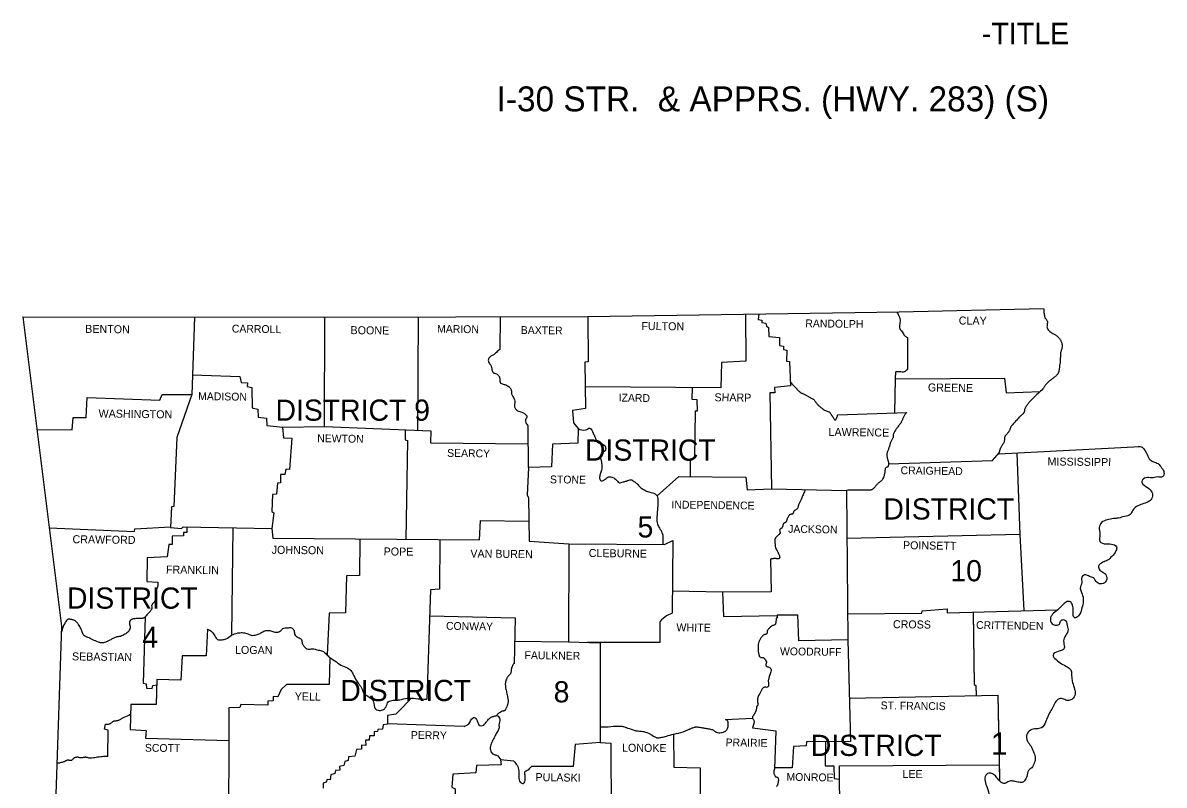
# Model space of a CAD drawing. Extents: x 541267 to 698737, y 790528 to 880942.
# Drawn here: x 637378 to 662478, y 852235 to 869007 of the extents above; entities that cross this region are included whole.
import ezdxf

# ---------------------------------------------------------------- set-up
doc = ezdxf.new("R2010")
doc.units = 0
doc.layers.add('R_Draft', color=7, linetype='Continuous')
doc.layers.add('R_Grid Annot', color=7, linetype='Continuous')

msp = doc.modelspace()

# ---------------------------------------------------------------- linework, layer by layer
at = {"layer": 'R_Draft'}
for p, q in [((656570, 861176), (656573, 861328)), ((658844, 859527), (658888, 859663)), ((653967, 855984), (654424, 855984))]:
    msp.add_line(p, q, dxfattribs=at)
for points in [[(637378, 862535), (643995, 862531), (649801, 862543), (656651, 862650), (659826, 862723)], [(637378, 862535), (638225, 855734), (637857, 844633)], [(641156, 862533), (641097, 860833)], [(641112, 861259), (642153, 861226), (642178, 861095), (642317, 861090), (642313, 861009), (642411, 860984), (642419, 860538), (642546, 860509), (642554, 860334), (642734, 860309), (642742, 860145), (643098, 860108), (644015, 860129), (644023, 862531)], [(646074, 862535), (646061, 860043)], [(647874, 862539), (647866, 861819)], [(649801, 862543), (649809, 861545), (649740, 861541), (649752, 860522), (649466, 860481), (649490, 860207), (649588, 860080), (649580, 859757), (649024, 859736), (649003, 859237), (648496, 859221), (648471, 858615), (648500, 858566), (648512, 857600), (649388, 857543), (649376, 855386), (650071, 855366), (650071, 853173), (649523, 853132), (649482, 852649), (648561, 852645)], [(653267, 862597), (653275, 861565), (652743, 861537), (652727, 860980), (649746, 860997)], [(653565, 862602), (653549, 862478), (653631, 862465), (653627, 862416), (653721, 862396), (653729, 862330), (653774, 862302), (653787, 862105), (654020, 862081), (654020, 861905), (654106, 861893), (654106, 861823), (654179, 861802), (654175, 861565), (654241, 861553), (654257, 861017), (653909, 860984), (653914, 860870), (653807, 860865), (653844, 858754), (655493, 858717), (655522, 855436), (654445, 855407), (654424, 855984)], [(656831, 862085), (656831, 861393)], [(656552, 860426), (656570, 861176), (656573, 861176), (658967, 861189), (659000, 860870), (659751, 860897)], [(652097, 860984), (652088, 860730), (652203, 860722), (652207, 860460), (652166, 860460), (652150, 859429), (652056, 859388), (652056, 859025)], [(637686, 860059), (638466, 860055), (638487, 860325), (638769, 860325), (638794, 860763), (640390, 860706), (640439, 860829), (641097, 860833), (640766, 859883), (640701, 858365), (640651, 858361), (640627, 857903), (640868, 857882), (640905, 857919), (642857, 857882), (642877, 857666)], [(655301, 860383), (656809, 860435)], [(643090, 860109), (643107, 859879), (643295, 859867), (643246, 859180), (643160, 859184), (643143, 859073), (643045, 859073), (643041, 858885), (642980, 858881), (642959, 858639), (642869, 858627), (642857, 858259), (642898, 858230), (642857, 857882)], [(644015, 860129), (646347, 860031), (646343, 859765), (648493, 859748)], [(645787, 860054), (645783, 859830), (645836, 859818), (645803, 857642)], [(648496, 859221), (648492, 860141)], [(658844, 859527), (661950, 859687)], [(656416, 859302), (658701, 859376), (658851, 859549)], [(659236, 859548), (659307, 857752), (659390, 856075)], [(651327, 858599), (651802, 859028), (653275, 859008), (653304, 858734), (653844, 858754)], [(656029, 858725), (655530, 858725), (655493, 858717)], [(642877, 857666), (647420, 857629), (647440, 858058), (648506, 858046)], [(637955, 857900), (639833, 857813), (639841, 857878), (640628, 857916)], [(640987, 857918), (640987, 857792), (640909, 857792), (640913, 857719), (640664, 857715), (640660, 857531), (640590, 857531), (640553, 857256), (640111, 857236), (640107, 856716), (640345, 856700)], [(641998, 857899), (641969, 855538)], [(659307, 857752), (655502, 857665)], [(644786, 857650), (644781, 856849), (644499, 856844), (644474, 856030), (644114, 856018), (644070, 855100)], [(646548, 857636), (646540, 856549), (646343, 856532), (646266, 854126)], [(649388, 857543), (651491, 857531), (651671, 857617), (651659, 856017), (651536, 855963), (651426, 855869), (651389, 855832), (651385, 855374), (649793, 855374)], [(653823, 857207), (653832, 856487), (652768, 856483), (651663, 856504)], [(652768, 856483), (652784, 855947), (653967, 855968)], [(640068, 855942), (640025, 854482), (640087, 854466), (640099, 854368), (640222, 854359), (640234, 854429), (640321, 854443)], [(646325, 855964), (648205, 855918), (648181, 854908)], [(653967, 855984), (653967, 855914), (653946, 855910)], [(655517, 856008), (657150, 856017), (657154, 856074), (657703, 856115), (657703, 856029), (660140, 856096)], [(658275, 856045), (658296, 854453), (658333, 854429), (658346, 854203)], [(658276, 856029), (658296, 854453), (658333, 854429), (658345, 854216)], [(658276, 856029), (658296, 854453), (658333, 854429), (658345, 854216)], [(658276, 856029), (658296, 854453), (658333, 854429), (658345, 854216)], [(658276, 856029), (658296, 854453), (658333, 854429), (658345, 854216)], [(641441, 855669), (641413, 855084), (640881, 855080), (640852, 854548), (640324, 854560), (640308, 854012), (639755, 854007), (639739, 853459), (640087, 853439), (640074, 853271), (641905, 853220)], [(655522, 855436), (655583, 853193), (654609, 853189), (654605, 853099), (654323, 853083), (654298, 852616), (653910, 852616)], [(648185, 855403), (649376, 855386)], [(644130, 855043), (644113, 854453), (643180, 854449), (643058, 854343), (642988, 854179), (642886, 854188), (642882, 854093), (642763, 854081), (642767, 853995), (642174, 854012), (642153, 853946), (641908, 853938), (641905, 853220)], [(655557, 854146), (658820, 854212)], [(658820, 854212), (658853, 852420)], [(658820, 854212), (658853, 852420)], [(658820, 854212), (658853, 852420)], [(658820, 854212), (658853, 852420)], [(658820, 854212), (658853, 852420)], [(658820, 854212), (658853, 852420)], [(658820, 854212), (658853, 852420)], [(658820, 854212), (658854, 852338)], [(645920, 854148), (645738, 853950), (645578, 853799), (645394, 853770), (645394, 853578), (645304, 853566), (645288, 853467), (645185, 853459), (645177, 853414), (645108, 853410), (645104, 853324), (645005, 853320), (644997, 853222), (644915, 853222), (644919, 853107), (644829, 853115), (644825, 853025), (644715, 853017), (644682, 852870), (644543, 852858), (644531, 852776), (644457, 852755), (644437, 852669), (644342, 852649), (644351, 852563), (644256, 852555), (644240, 852489), (644154, 852465), (644134, 852354), (644068, 852358), (644048, 852301), (643986, 852281), (643982, 852170)], [(652833, 853680), (653422, 853709)], [(639244, 852866), (639256, 853443), (639174, 853467), (639199, 853578)], [(647084, 853529), (645394, 853582)], [(653427, 853496), (653938, 853431), (653909, 852596)], [(641905, 853220), (641899, 851544), (641695, 851540), (641711, 851417), (641515, 851421), (641511, 851331), (641318, 851331), (641323, 851266), (641036, 851258), (641032, 851008), (640754, 851033), (640709, 849019), (639133, 849024), (639096, 848557), (639154, 848516), (639150, 847992), (637970, 848044)], [(650071, 853173), (650308, 853156), (650313, 851593), (650100, 850705), (650554, 850685), (650550, 849903)], [(651687, 853361), (651696, 852629), (652273, 852616), (652277, 851045)], [(655027, 853191), (655022, 852661), (655211, 852661), (655219, 852379), (655340, 852366)], [(648177, 852764), (647882, 852796), (647894, 852686), (647358, 852665), (647342, 852506), (646838, 852477), (646810, 852191), (646884, 852154), (646884, 851966)], [(655508, 849028), (655890, 849052), (655886, 849883), (655587, 849903), (655603, 851528), (655346, 851565), (655338, 852657), (658848, 852682)]]:
    msp.add_lwpolyline(points, dxfattribs=at)
for points in [[(659826, 862723), (659830, 862678), (659835, 862633), (659840, 862588), (659847, 862543), (659856, 862518), (659873, 862495), (659891, 862473), (659904, 862449), (659909, 862407), (659904, 862363), (659901, 862318), (659904, 862297), (659912, 862277), (659943, 862237), (659982, 862203), (660011, 862184), (660041, 862167), (660072, 862150), (660101, 862130), (660160, 862077), (660185, 862047), (660196, 862030), (660207, 862011), (660222, 861977), (660230, 861942), (660233, 861907), (660232, 861872), (660224, 861836), (660214, 861801), (660205, 861765), (660199, 861729), (660197, 861689), (660195, 861649), (660193, 861609), (660191, 861569), (660174, 861430), (660167, 861366), (660160, 861334), (660156, 861319), (660150, 861303), (660107, 861247), (660051, 861201), (660028, 861182), (660004, 861164), (659980, 861146), (659957, 861127), (659871, 861041), (659855, 861019), (659842, 860996), (659827, 860972), (659810, 860951), (659704, 860853), (659597, 860751), (659511, 860661), (659488, 860634), (659466, 860605), (659445, 860576), (659425, 860546), (659413, 860516), (659407, 860482), (659400, 860448), (659394, 860433), (659384, 860419), (659362, 860396), (659338, 860374), (659313, 860352), (659290, 860329), (659217, 860248), (659118, 860137), (659102, 860112), (659091, 860083), (659081, 860054), (659069, 860027), (659047, 859994), (659022, 859964), (658996, 859933), (658975, 859900), (658966, 859870), (658964, 859839), (658962, 859807), (658955, 859777), (658941, 859752), (658925, 859727), (658909, 859703), (658893, 859679), (658888, 859663)], [(656593, 862649), (656667, 862494), (656663, 862384), (656663, 862281), (656717, 862212), (656770, 862126), (656831, 862085)], [(647866, 861819), (647792, 861757), (647726, 861700), (647628, 861631), (647616, 861565), (647649, 861500), (647681, 861446), (647694, 861373), (647722, 861311), (647792, 861287), (647849, 861234), (647870, 861160), (647878, 861090), (647943, 861058), (648017, 861033), (648087, 860984), (648119, 860923), (648127, 860845), (648156, 860784), (648189, 860710), (648197, 860649), (648189, 860587), (648205, 860530), (648258, 860473), (648353, 860444), (648418, 860403), (648463, 860346), (648434, 860276), (648438, 860215), (648492, 860141)], [(656831, 861393), (656762, 861328), (656659, 861328), (656573, 861328)], [(654255, 861103), (654323, 861031), (654392, 860960), (654402, 860950), (654430, 860920), (654450, 860900), (654460, 860891), (654465, 860886), (654470, 860882), (654491, 860868), (654514, 860857), (654537, 860848), (654560, 860837), (654613, 860806), (654666, 860775), (654690, 860763), (654714, 860752), (654749, 860733), (654755, 860730), (654761, 860726), (654779, 860710), (654793, 860689), (654807, 860668), (654814, 860658), (654822, 860649), (654864, 860605), (654908, 860563), (654929, 860544), (654950, 860527), (654972, 860510), (654994, 860493), (655027, 860476), (655064, 860464), (655100, 860450), (655116, 860441), (655123, 860435), (655129, 860428), (655141, 860411), (655152, 860393), (655163, 860376), (655174, 860358), (655181, 860347), (655189, 860335), (655205, 860311), (655220, 860289), (655228, 860280), (655231, 860276), (655233, 860274), (655235, 860272), (655240, 860269), (655244, 860269), (655254, 860274), (655271, 860303), (655287, 860345), (655294, 860365), (655301, 860383)], [(656809, 860435), (656775, 860386), (656745, 860334), (656732, 860305), (656721, 860276), (656710, 860247), (656696, 860219), (656673, 860185), (656648, 860153), (656622, 860121), (656598, 860088), (656558, 860026), (656540, 859994), (656524, 859961), (656519, 859940), (656517, 859918), (656516, 859896), (656512, 859875), (656499, 859846), (656483, 859818), (656467, 859790), (656455, 859761), (656446, 859732), (656438, 859703), (656430, 859675), (656422, 859646), (656413, 859621), (656403, 859597), (656393, 859573), (656385, 859548), (656380, 859523), (656380, 859497), (656382, 859471), (656385, 859446), (656391, 859420), (656399, 859394), (656407, 859369), (656414, 859343), (656416, 859320), (656416, 859296), (656412, 859272), (656409, 859261), (656406, 859249), (656393, 859235), (656374, 859227), (656355, 859218), (656344, 859204), (656341, 859190), (656339, 859175), (656336, 859145), (656333, 859115), (656328, 859085), (656317, 859044), (656303, 859004), (656281, 858960), (656266, 858940), (656250, 858922), (656231, 858905), (656211, 858891), (656191, 858876), (656172, 858860), (656151, 858838), (656132, 858814), (656112, 858789), (656090, 858766), (656062, 858744), (656046, 858734), (656029, 858725)], [(649588, 860080), (649752, 860051), (649850, 860088), (649920, 859982), (649957, 859900), (650018, 859781), (650116, 859744), (650190, 859679), (650190, 859609), (650124, 859544), (650075, 859478), (650092, 859401), (650108, 859294), (650108, 859192), (650083, 859098), (650063, 859012), (650083, 858938), (650161, 858950), (650243, 859012), (650329, 859012), (650411, 858967), (650497, 858889), (650583, 858905), (650652, 858926), (650750, 858955), (650820, 858918), (650881, 858869), (650955, 858791), (651025, 858742), (651115, 858697), (651225, 858668), (651327, 858599), (651344, 858480), (651340, 858378), (651331, 858251), (651323, 858112), (651336, 857977), (651381, 857887), (651438, 857780), (651454, 857682), (651450, 857526)], [(661905, 859683), (661950, 859687), (662089, 859540), (662151, 859417), (662241, 859347), (662343, 859311), (662421, 859216), (662474, 859114), (662445, 859024), (662331, 859016), (662204, 858995), (662081, 859000), (661983, 858918), (662073, 858807), (662192, 858705), (662224, 858594), (662159, 858488), (662028, 858431), (661901, 858382), (661786, 858283), (661733, 858189), (661606, 858148), (661475, 858112), (661361, 858099), (661230, 858075), (661103, 858013), (661050, 857907), (661066, 857756), (661062, 857596), (661197, 857543), (661316, 857539), (661430, 857477), (661418, 857387), (661332, 857273), (661230, 857183), (661128, 857138), (661034, 857052), (661066, 856966), (661152, 856909), (661214, 856814), (661205, 856729), (661107, 856667), (661001, 856692), (660923, 856794), (660833, 856827), (660755, 856864), (660665, 856810), (660665, 856692), (660633, 856565), (660661, 856471), (660698, 856340), (660694, 856242), (660661, 856103), (660592, 855959), (660510, 855914), (660477, 856070), (660461, 856197), (660412, 856270), (660346, 856274), (660260, 856213), (660166, 856119), (660047, 856017), (659978, 855914), (660015, 855787), (660105, 855755), (660174, 855779), (660211, 855861), (660281, 855873), (660346, 855747)], [(654583, 858738), (654547, 858645), (654507, 858554), (654493, 858523), (654478, 858492), (654464, 858461), (654450, 858431), (654439, 858405), (654431, 858378), (654423, 858351), (654413, 858324), (654398, 858306), (654376, 858291), (654354, 858279), (654344, 858271), (654335, 858263), (654328, 858250), (654323, 858234), (654318, 858219), (654310, 858206), (654295, 858197), (654276, 858194), (654256, 858190), (654241, 858181), (654233, 858172), (654226, 858162), (654212, 858142), (654199, 858121), (654188, 858099), (654181, 858081), (654176, 858062), (654171, 858043), (654163, 858026), (654151, 858015), (654135, 858009), (654118, 858003), (654106, 857993), (654100, 857983), (654096, 857972), (654091, 857948), (654086, 857924), (654080, 857908), (654077, 857903), (654066, 857890), (654050, 857879), (654035, 857867), (654024, 857854), (654022, 857834), (654028, 857812), (654033, 857790), (654028, 857772), (654025, 857768), (654021, 857764), (653998, 857743), (653982, 857730), (653967, 857715), (653953, 857700), (653939, 857684), (653927, 857668), (653922, 857659), (653918, 857649), (653913, 857604), (653918, 857559), (653921, 857529), (653924, 857499), (653929, 857470), (653933, 857455), (653938, 857441), (653947, 857422), (653958, 857405), (653969, 857388), (653979, 857371), (653999, 857326), (654008, 857304), (654016, 857281), (654020, 857266), (654023, 857251), (654021, 857236), (654017, 857229), (654015, 857226), (654012, 857224), (653987, 857214), (653961, 857217), (653935, 857223), (653922, 857224), (653909, 857224), (653888, 857220), (653866, 857216), (653845, 857212), (653823, 857207)], [(640345, 856700), (640348, 856679), (640350, 856657), (640345, 856614), (640337, 856591), (640328, 856569), (640320, 856547), (640312, 856524), (640291, 856446), (640291, 856421), (640298, 856395), (640304, 856369), (640305, 856357), (640304, 856344), (640289, 856302), (640267, 856262), (640254, 856245), (640240, 856229), (640225, 856214), (640214, 856197), (640210, 856177), (640214, 856156), (640217, 856134), (640214, 856115), (640207, 856103), (640200, 856092), (640186, 856070), (640170, 856049), (640152, 856029), (640087, 855963), (640061, 855934), (640047, 855920), (640038, 855915), (640034, 855912), (640029, 855910), (640004, 855903), (639979, 855902), (639953, 855902), (639940, 855902), (639927, 855902), (639884, 855900), (639841, 855898), (639819, 855896), (639797, 855891), (639776, 855883), (639766, 855877), (639755, 855869), (639742, 855856), (639732, 855841), (639726, 855825), (639723, 855808), (639724, 855784), (639730, 855761), (639737, 855737), (639739, 855714), (639735, 855691), (639729, 855668), (639706, 855624), (639666, 855584), (639620, 855554), (639574, 855529), (639526, 855509), (639502, 855504), (639477, 855502), (639452, 855500), (639428, 855493), (639394, 855477), (639360, 855460), (639327, 855444), (639293, 855427), (639170, 855374), (639138, 855367), (639104, 855366), (639071, 855372), (639039, 855382), (638916, 855436), (638806, 855485), (638783, 855494), (638760, 855504), (638739, 855517), (638729, 855525), (638724, 855529), (638720, 855534), (638697, 855569), (638681, 855608), (638667, 855647), (638659, 855666), (638650, 855685), (638629, 855726), (638605, 855767), (638590, 855790), (638572, 855811), (638551, 855831), (638540, 855840), (638528, 855849), (638505, 855862), (638481, 855871), (638458, 855877), (638434, 855882), (638414, 855885), (638393, 855888), (638373, 855885), (638364, 855880), (638360, 855877), (638356, 855873), (638301, 855800), (638265, 855724), (638241, 855646), (638219, 855566)], [(653946, 855910), (653944, 855876), (653941, 855842), (653935, 855809), (653931, 855792), (653929, 855783), (653926, 855775), (653913, 855760), (653892, 855753), (653868, 855748), (653857, 855744), (653848, 855738), (653800, 855696), (653758, 855648), (653750, 855629), (653748, 855607), (653746, 855585), (653738, 855566), (653730, 855560), (653721, 855556), (653701, 855550), (653681, 855544), (653664, 855534), (653645, 855514), (653626, 855494), (653609, 855472), (653594, 855448), (653566, 855390), (653549, 855329), (653546, 855268), (653549, 855206), (653552, 855171), (653557, 855136), (653565, 855101), (653571, 855084), (653578, 855067), (653597, 855051), (653625, 855046), (653656, 855043), (653680, 855030), (653688, 855021), (653696, 855012), (653709, 854991), (653729, 854949), (653730, 854927), (653724, 854905), (653719, 854883), (653721, 854863), (653740, 854845), (653769, 854835), (653798, 854825), (653819, 854805), (653826, 854793), (653833, 854781), (653837, 854769), (653836, 854756), (653819, 854703), (653774, 854552), (653771, 854527), (653773, 854501), (653777, 854475), (653778, 854449), (653777, 854427), (653774, 854415), (653770, 854404), (653749, 854389), (653716, 854388), (653683, 854389), (653660, 854376), (653594, 854265), (653549, 854188), (653544, 854175), (653535, 854137), (653534, 854111), (653533, 854085), (653535, 854067), (653540, 854048), (653545, 854030), (653545, 854012), (653540, 853996), (653530, 853982), (653520, 853969), (653513, 853954), (653509, 853933), (653509, 853911), (653507, 853889), (653500, 853868), (653459, 853795), (653422, 853725), (653424, 853705), (653440, 853685), (653457, 853664), (653463, 853643), (653458, 853615), (653451, 853586), (653445, 853563), (653438, 853541), (653427, 853496)], [(641441, 855669), (641531, 855611), (641601, 855517), (641662, 855440), (641764, 855436), (641846, 855452), (641969, 855538)], [(641969, 855538), (642104, 855583), (642202, 855591), (642301, 855575), (642403, 855534), (642513, 855542), (642595, 855571), (642677, 855624), (642767, 855640), (642853, 855624), (642943, 855599), (643041, 855628), (643098, 855681), (643197, 855697), (643283, 855697), (643344, 855628), (643356, 855554), (643434, 855485), (643504, 855440), (643524, 855354), (643561, 855292), (643598, 855251), (643651, 855227), (643741, 855235), (643880, 855206), (643970, 855186), (644052, 855116), (644130, 855043)], [(660346, 855747), (660362, 855628), (660293, 855501), (660268, 855374), (660281, 855247), (660150, 855178), (660035, 855096), (660101, 854998), (660223, 854908), (660346, 854838), (660424, 854769), (660444, 854601), (660465, 854494), (660506, 854347), (660522, 854245), (660448, 854122), (660362, 854097), (660272, 854126), (660166, 854134), (660080, 854052), (660019, 853938), (659957, 853823), (659912, 853725), (659867, 853619), (659777, 853496), (659667, 853476), (659536, 853443), (659458, 853353), (659470, 853201), (659544, 853099), (659601, 852972), (659642, 852862), (659622, 852723), (659565, 852620), (659491, 852559), (659458, 852428), (659405, 852330), (659356, 852297), (659258, 852305), (659151, 852326), (659061, 852318), (658975, 852273), (658889, 852301), (658799, 852399), (658726, 852473), (658644, 852502), (658558, 852457), (658542, 852322), (658582, 852183), (658619, 851994), (658582, 851880), (658570, 851691)], [(644130, 855043), (644273, 854945), (644408, 854859), (644547, 854797), (644625, 854707), (644694, 854568), (644752, 854482), (644825, 854376), (644878, 854257), (644964, 854192), (645054, 854134), (645099, 854032), (645120, 853930), (645218, 853881), (645312, 853901), (645365, 853962), (645414, 854069), (645525, 854102), (645668, 854114), (645832, 854151), (646012, 854143), (646266, 854126)], [(648181, 854908), (648175, 854909), (648168, 854904), (648154, 854879), (648140, 854845), (648134, 854828), (648127, 854814), (648119, 854783), (648116, 854751), (648112, 854720), (648109, 854705), (648103, 854691), (648089, 854670), (648071, 854652), (648053, 854633), (648037, 854613), (648025, 854592), (648013, 854570), (647997, 854523), (647994, 854508), (647991, 854493), (647988, 854464), (647989, 854434), (647992, 854404), (648013, 854298), (648033, 854196), (648042, 854149), (648046, 854125), (648050, 854102), (648051, 854072), (648046, 854042), (648038, 854013), (648034, 853998), (648029, 853983), (648020, 853955), (648009, 853929), (647995, 853904), (647986, 853892), (647981, 853886), (647976, 853881), (647957, 853869), (647936, 853864), (647914, 853860), (647894, 853852), (647881, 853842), (647867, 853833), (647840, 853813), (647816, 853790), (647795, 853765)], [(639199, 853578), (639221, 853575), (639244, 853575), (639278, 853582), (639283, 853584), (639289, 853586), (639300, 853592), (639311, 853599), (639332, 853615), (639352, 853631), (639369, 853641), (639375, 853643), (639389, 853647), (639403, 853650), (639432, 853654), (639462, 853659), (639476, 853662), (639489, 853668), (639518, 853683), (639546, 853699), (639575, 853715), (639604, 853729), (639749, 853795)], [(647084, 853529), (647186, 853586), (647240, 853672), (647305, 853725), (647370, 853651), (647428, 853545), (647489, 853545), (647567, 853619), (647616, 853684), (647677, 853733), (647743, 853754), (647812, 853762), (647866, 853684), (647849, 853561), (647849, 853480), (647804, 853394), (647755, 853304), (647702, 853201), (647661, 853091), (647669, 852985), (647726, 852915), (647792, 852894), (647891, 852795)], [(650071, 853516), (650308, 853525), (650534, 853533), (650606, 853518), (650641, 853505), (650659, 853498), (650677, 853492), (650840, 853439), (650864, 853433), (650888, 853430), (650937, 853426), (650985, 853423), (651033, 853414), (651168, 853361), (651188, 853351), (651208, 853339), (651247, 853314), (651306, 853283), (651317, 853281), (651327, 853279), (651352, 853278), (651429, 853288), (651481, 853302), (651532, 853316), (651692, 853357), (651900, 853410), (651935, 853422), (651968, 853437), (652001, 853453), (652035, 853467), (652054, 853475), (652112, 853499), (652151, 853511), (652171, 853515), (652191, 853516), (652268, 853510), (652346, 853496), (652435, 853481), (652522, 853463), (652552, 853451), (652579, 853432), (652606, 853413), (652633, 853398), (652681, 853388), (652733, 853391), (652785, 853404), (652810, 853414), (652833, 853426), (652858, 853449), (652876, 853483), (652892, 853565), (652879, 853642), (652860, 853668), (652833, 853680)], [(639244, 852866), (639214, 852866), (639184, 852866), (639125, 852862), (638990, 852845), (638867, 852829), (638853, 852829), (638840, 852830), (638812, 852837), (638784, 852845), (638764, 852849), (638757, 852849), (638731, 852847), (638706, 852842), (638680, 852836), (638655, 852833), (638637, 852836), (638620, 852841), (638602, 852847), (638585, 852849), (638563, 852848), (638542, 852844), (638521, 852838), (638499, 852829), (638485, 852818), (638474, 852804), (638464, 852789), (638450, 852780), (638438, 852777), (638425, 852777), (638399, 852780), (638373, 852783), (638354, 852782), (638348, 852780), (638329, 852772), (638311, 852763), (638293, 852754), (638274, 852747), (638237, 852736), (638200, 852727), (638162, 852719), (638125, 852714)], [(648177, 852764), (648246, 852674), (648287, 852551), (648287, 852412), (648320, 852297), (648385, 852273), (648426, 852371), (648418, 852469), (648418, 852526), (648488, 852575), (648561, 852645)], [(653909, 852596), (653905, 852586), (653901, 852576), (653896, 852555), (653893, 852534), (653893, 852524), (653893, 852514), (653896, 852492), (653903, 852470), (653913, 852449), (653919, 852438), (653926, 852428), (653931, 852422), (653939, 852418), (653956, 852414), (653972, 852410), (653979, 852406), (653981, 852403), (653983, 852399), (653985, 852394), (653987, 852389), (653993, 852358), (653994, 852338), (653993, 852328), (653991, 852318), (653983, 852276), (653978, 852256), (653975, 852246), (653971, 852236), (653963, 852219), (653954, 852203)]]:
    msp.add_spline(points, degree=3, dxfattribs=at)

# ---------------------------------------------------------------- texts
for s, height, rotation, p in [('RANDOLPH', 171.9, 359.2584, (654585, 862310)), ('CLAY', 175.9, 359.2258, (657960, 862371)), ('BENTON', 176, 359.2527, (638749, 862187)), ('CARROLL', 171.9, 359.1481, (641973, 862195)), ('BOONE', 176, 359.4001, (644584, 862158)), ('MARION', 171.9, 359.1854, (646487, 862191)), ('BAXTER', 171.9, 359.256, (648328, 862163)), ('FULTON', 175.9, 359.4996, (650980, 862249)), ('GREENE', 176, 359.2361, (657281, 860898)), ('MADISON', 171.9, 359.0906, (641232, 860710)), ('IZARD', 171.8, 358.9259, (650480, 860677)), ('SHARP', 175.9, 359.3905, (652588, 860681)), ('WASHINGTON', 175.9, 359.232, (639043, 860325)), ('NEWTON', 171.9, 359.2717, (643851, 859781)), ('LAWRENCE', 176, 359.2678, (655096, 859920)), ('SEARCY', 171.8, 359.2527, (646708, 859458)), ('MISSISSIPPI', 175.93, 359.3097, (659912, 859270)), ('CRAIGHEAD', 171.9, 359.1159, (656680, 859077)), ('STONE', 171.8, 359.4001, (648970, 858877)), ('INDEPENDENCE', 171.83, 359.2188, (651642, 858324)), ('JACKSON', 171.8, 359.1352, (654208, 857788)), ('CRAWFORD', 175.9, 359.2771, (638470, 857559)), ('JOHNSON', 176, 359.3514, (642849, 857326)), ('POPE', 176, 359.6155, (645312, 857289)), ('VAN BUREN', 176, 359.3508, (647219, 857244)), ('CLEBURNE', 175.9, 359.2535, (649822, 857256)), ('POINSETT', 175.9, 359.1987, (656733, 857428)), ('FRANKLIN', 176, 359.1816, (640525, 856892)), ('CONWAY', 171.8, 359.0372, (646683, 855656)), ('WHITE', 176, 359.3139, (651749, 855620)), ('CROSS', 175.9, 359.384, (656512, 855689)), ('CRITTENDEN', 171.9, 359.213, (658341, 855673)), ('SEBASTIAN', 175.9, 359.2816, (638458, 854981)), ('LOGAN', 176, 359.3969, (642043, 855125)), ('FAULKNER', 171.9, 359.2486, (648410, 855010)), ('WOODRUFF', 171.8, 359.2748, (654028, 855096)), ('YELL', 176, 359.1987, (643356, 854102)), ('ST. FRANCIS', 171.83, 359.2216, (656242, 853905)), ('PERRY', 171.9, 359.0858, (645910, 853255)), ('LONOKE', 176, 359.4974, (650554, 852972)), ('PRAIRIE', 171.9, 359.2116, (652833, 853091)), ('SCOTT', 171.9, 359.4063, (640062, 852972)), ('PULASKI', 176, 359.0531, (648651, 852326)), ('MONROE', 171.8, 359.0331, (654171, 852334)), ('LEE', 176, 359.4327, (656721, 852395))]:
    msp.add_text(s, height=height, rotation=rotation, dxfattribs=at).set_placement(p)
for s, height, p in [('DISTRICT 9', 466.5, (642935, 860252)), ('DISTRICT', 466.5, (649740, 859374)), ('DISTRICT', 466.5, (656303, 858079)), ('5', 466, (650897, 857685)), ('10', 466.5, (657777, 856720)), ('DISTRICT', 466.5, (638348, 856118)), ('4', 466, (640005, 855259)), ('DISTRICT', 466.5, (644359, 854085)), ('8', 466, (649052, 854057)), ('DISTRICT', 466.5, (654707, 852878)), ('1', 491, (658668, 852907))]:
    msp.add_text(s, height=height, dxfattribs=at).set_placement(p)
at = {"layer": 'R_Grid Annot'}
for s, height, p in [('-TITLE', 470.3, (658468, 868537)), ('I-30 STR.  & APPRS. (HWY. 283) (S)', 548.67, (647797, 867059))]:
    msp.add_text(s, height=height, dxfattribs=at).set_placement(p)

doc.saveas('drawing.dxf')
